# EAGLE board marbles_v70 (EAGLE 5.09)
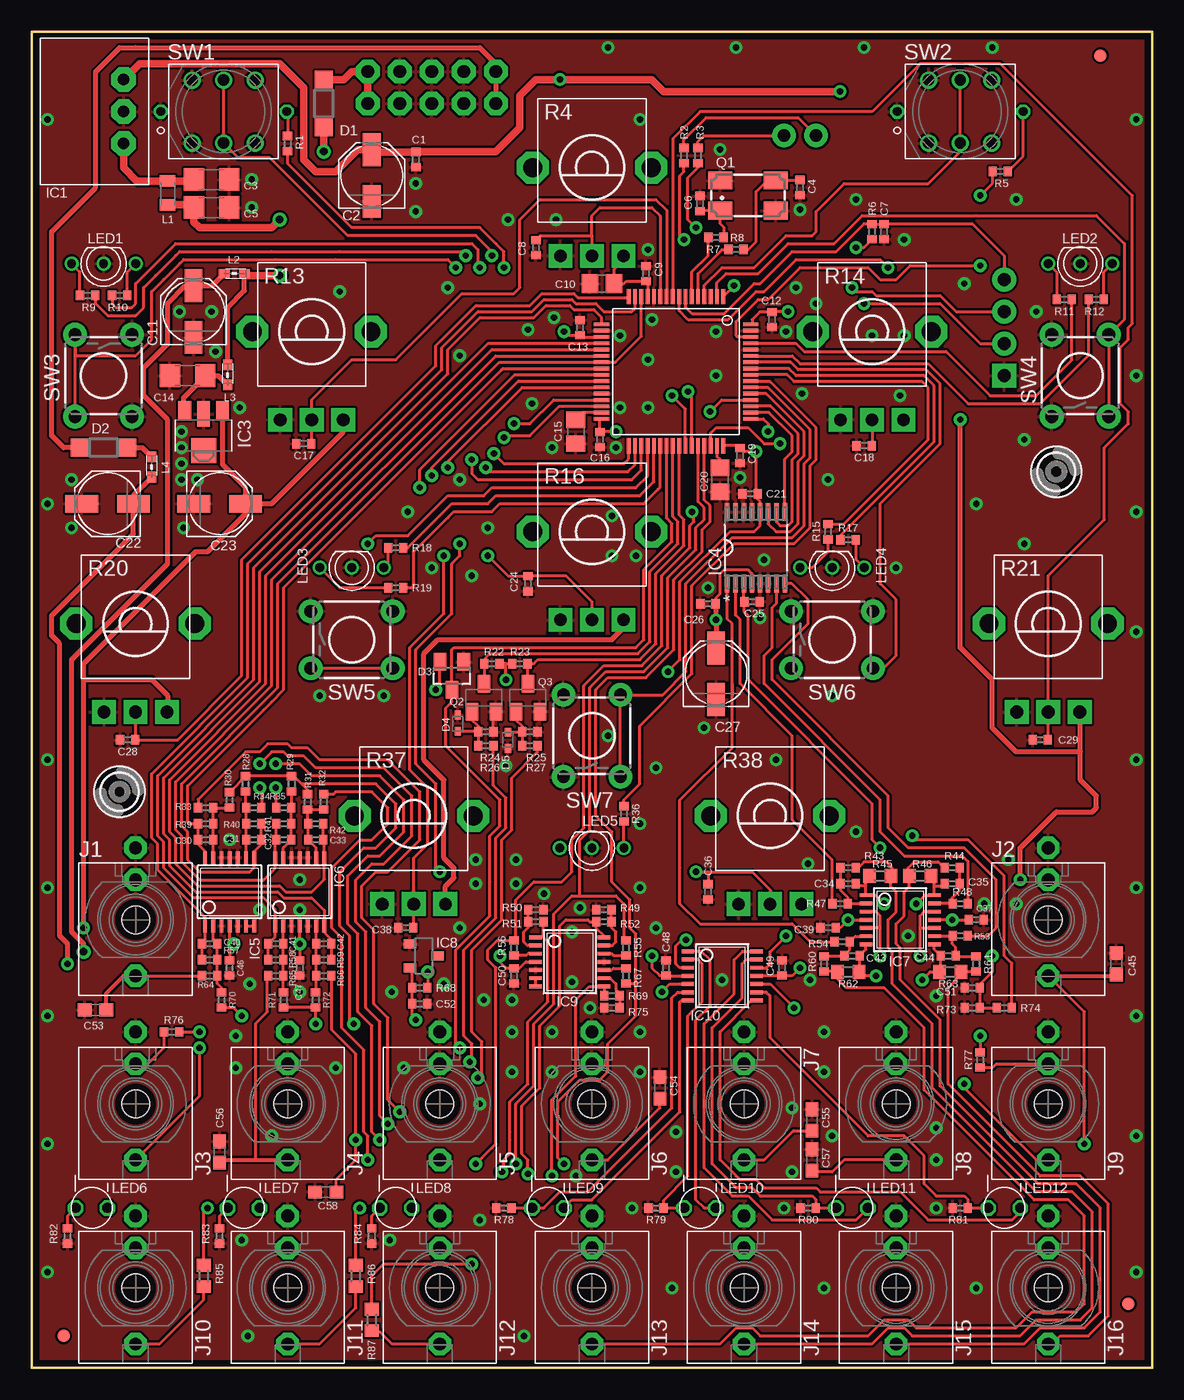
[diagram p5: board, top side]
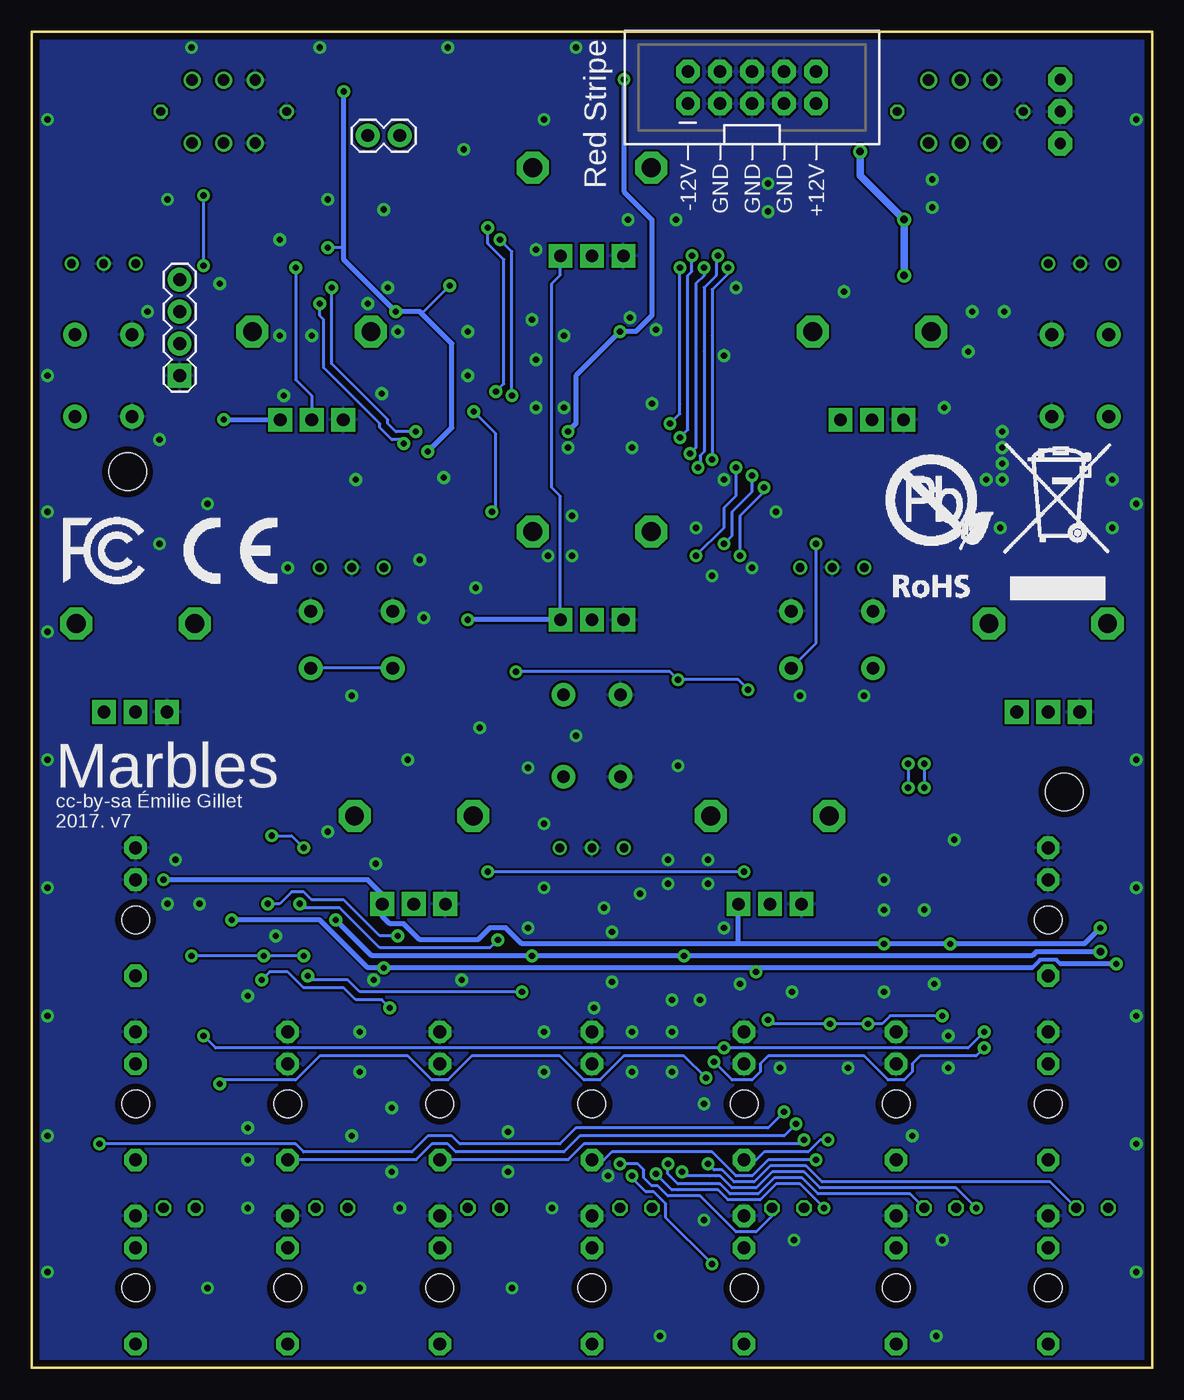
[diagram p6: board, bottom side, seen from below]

Size 88.9 x 106.05 mm. Coordinates in mm from the lower left corner, seen from the top.
Outline: 0,0 88.9,0 88.9,106.05 0,106.05 0,0
Copper layers (1*16): Top 0.035mm / dielectric 1.5mm / Bottom 0.035mm
Design rules "PCBCart-Standard-Fine": minimum track width 8mil, minimum drill 0.4mm, track to track 7mil, track to pad 7mil, pad to pad 7mil, via to via 7mil, smd to smd 7mil, copper to edge 20mil, drill to drill 8mil, minimum pad ring 8mil, minimum via ring 10mil, stop-mask expansion 3mil, vias tented up to drill 25mil, thermal gap 8mil

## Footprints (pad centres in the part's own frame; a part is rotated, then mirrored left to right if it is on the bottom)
C0402 = smd 0.65 x 0.75: 1 -0.6,0; 2 0.6,0
PANASONIC_C = smd 2.6 x 1.4: + 2.05,0; - -2.05,0
C1206 = smd 1.6 x 1.8: 1 -1.4,0; 2 1.4,0
C0805 = smd 1.3 x 1.5: 1 -0.95,0; 2 0.95,0
C0603 = smd 1.1 x 1: 1 -0.85,0; 2 0.85,0
SOD123 = smd 1.4 x 1.4: A 1.9,0; C -1.9,0
SOT23 = smd 1 x 1.4: 1 -0.95,-1.1; 2 0.95,-1.1; 3 0,1.1
SOD523 = smd 0.7 x 0.5: A 0.7,0; C -0.6,0
FIDUCIAL-1X2 = smd 1 x 1: 1 0,0
3,0TINY = hole 3: 0,0
WE78 = drill 0.9 pad 1.93 octagon: 1 -2.54,0; 2 0,0; 3 2.54,0
TQFP-10X10-64 = smd 1.2 x 0.3: 1 -5.936,3.75; 2 -5.936,3.25; 3 -5.936,2.75; 4 -5.936,2.25; 5 -5.936,1.75; 6 -5.936,1.25; 7 -5.936,0.75; 8 -5.936,0.25; 9 -5.936,-0.25; 10 -5.936,-0.75; 11 -5.936,-1.25; 12 -5.936,-1.75; 13 -5.936,-2.25; 14 -5.936,-2.75; 15 -5.936,-3.25; 16 -5.936,-3.75; 33 5.886,-3.75; 34 5.886,-3.25; 35 5.886,-2.75; 36 5.886,-2.25; 37 5.886,-1.75; 38 5.886,-1.25; 39 5.886,-0.75; 40 5.886,-0.25; 41 5.886,0.25; 42 5.886,0.75; 43 5.886,1.25; 44 5.886,1.75; 45 5.886,2.25; 46 5.886,2.75; 47 5.886,3.25; 48 5.886,3.75 | smd 0.3 x 1.2: 17 -3.75,-5.911; 18 -3.25,-5.911; 19 -2.75,-5.911; 20 -2.25,-5.911; 21 -1.75,-5.911; 22 -1.25,-5.911; 23 -0.75,-5.911; 24 -0.25,-5.911; 25 0.25,-5.911; 26 0.75,-5.911; 27 1.25,-5.911; 28 1.75,-5.911; 29 2.25,-5.911; 30 2.75,-5.911; 31 3.25,-5.911; 32 3.75,-5.911; 49 3.75,5.936; 50 3.25,5.936; 51 2.75,5.936; 52 2.25,5.936; 53 1.75,5.936; 54 1.25,5.936; 55 0.75,5.936; 56 0.25,5.936; 57 -0.25,5.936; 58 -0.75,5.936; 59 -1.25,5.936; 60 -1.75,5.936; 61 -2.25,5.936; 62 -2.75,5.936; 63 -3.25,5.936; 64 -3.75,5.936
SOT89 = smd 1 x 1.5: 1 -1.499,-1.981; 3 1.499,-1.981 | smd 1 x 2: 2 0,-1.727 | smd 2 x 2: 2@1 0,1.194
SOP65P640X110-16N = smd 1.422 x 0.356: 1 -2.845,2.286; 2 -2.845,1.626; 3 -2.845,0.965; 4 -2.845,0.33; 5 -2.845,-0.33; 6 -2.845,-0.965; 7 -2.845,-1.626; 8 -2.845,-2.286; 9 2.845,-2.286; 10 2.845,-1.626; 11 2.845,-0.965; 12 2.845,-0.33; 13 2.845,0.33; 14 2.845,0.965; 15 2.845,1.626; 16 2.845,2.286
TSSOP14_065 = smd 0.305 x 0.991: 1 -1.95,-2.718; 2 -1.3,-2.718; 3 -0.65,-2.718; 4 0,-2.718; 5 0.65,-2.718; 6 1.3,-2.718; 7 1.95,-2.718; 8 1.95,2.718; 9 1.3,2.718; 10 0.65,2.718; 11 0,2.718; 12 -0.65,2.718; 13 -1.3,2.718; 14 -1.95,2.718
DBZ_R-PDSO-G3 = smd 0.7 x 1: 1 -0.95,-1.1; 2 0.95,-1.1; 3 0,1.1
WQP_PJ_301M6 = drill 1.016 pad 1.778 octagon: P1 0,-5.715; P2 0,-3.175; P3 0,4.445 | hole 2.2: 0,0
1X04 = drill 1.016 pad 1.88 square: 1 0,0 | drill 1.016 pad 1.88 round: 2 2.54,0; 3 5.08,0; 4 7.62,0
1X02 = drill 1.016 pad 1.88 round: 1 0,0; 2 2.54,0
2X5-SHROUDED = drill 1.016 pad 1.88 octagon: 1 -1.27,5.08; 2 1.27,5.08; 3 -1.27,2.54; 4 1.27,2.54; 5 -1.27,0; 6 1.27,0; 7 -1.27,-2.54; 8 1.27,-2.54; 9 -1.27,-5.08; 10 1.27,-5.08
L2012C = smd 0.9 x 1.25: 1 -0.9,0; 2 1,0
0603 = smd 0.85 x 0.7: 1 -0.9,0; 2 0.7,0
LED-BICOLOR-THROUGHHOLE-2.54 = drill 0.7 round: 1 -2.54,0; 2 0,0; 3 2.54,0
LED3MM = drill 0.813 octagon: 1 -1.27,0; 2 1.27,0
CTS406 = smd 1.9 x 1.4: 1 -2.2,-1.2; 2 2.2,-1.2; 3 2.2,1.2; 4 -2.2,1.2
SOT23-BEC = smd 1 x 1.4: B -0.95,-1.1; C 0,1.1; E 0.95,-1.1
R0402 = smd 0.65 x 0.75: 1 -0.6,0; 2 0.6,0
ALPS_POT_VERTICAL_PS = drill 1 pad 1.88 square: P$1 -2.5,7; P$2 0,7; P$3 2.5,7 | drill 1.5 pad 2.54 octagon: P$4 -4.7,0; P$5 4.7,0
R0603 = smd 1 x 1.1: 1 -0.85,0; 2 0.85,0
LP4OA1PBCT = drill 0.7 octagon: L1 5,0; L2 -5,0 | drill 0.9 round: P1 2.5,2.5; P2 0,2.5; P3 -2.5,2.5; P4 2.5,-2.5; P5 0,-2.5; P6 -2.5,-2.5
TACTILE-PTH = drill 1.016 pad 1.88 round: 1 -3.251,2.261; 2 3.251,2.261; 3 -3.251,-2.261; 4 3.251,-2.261

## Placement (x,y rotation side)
C1  100n  [C0402]  30.48,95.89 270 top
C2  22u  [PANASONIC_C]  26.99,94.61 90 top
C3  22u  [C1206]  14.29,94.3 0 top
C4  20p  [C0402]  60.96,93.66 90 top
C5  22u  [C1206]  14.29,92.08 0 top
C6  20p  [C0402]  53.02,92.39 270 top
C7  100n  [C0402]  67.63,90.17 270 top
C8  100n  [C0402]  40.01,88.9 270 top
C9  100n  [C0402]  48.74,86.84 90 top
C10  2.2u  [C0805]  45.24,86.04 180 top
C11  22u  [PANASONIC_C]  12.86,83.82 90 top
C12  100n  [C0402]  58.74,83.19 270 top
C13  100n  [C0402]  43.5,82.55 90 top
C14  22u  [C1206]  12.38,78.74 180 top
C15  2.2u  [C0805]  43.18,74.3 270 top
C16  100n  [C0402]  45.09,73.66 270 top
C17  100n  [C0402]  21.59,73.34 180 top
C18  100n  [C0402]  66.04,73.18 180 top
C19  100n  [C0402]  56.2,72.39 270 top
C20  2.2u  [C0805]  54.61,70.48 270 top
C21  100n  [C0402]  56.99,69.37 180 top
C22  22u  [PANASONIC_C]  6.03,68.58 180 top
C23  22u  [PANASONIC_C]  14.92,68.58 0 top
C24  100n  [C0402]  39.37,62.23 270 top
C25  470n  [C0402]  57.15,60.8 0 top
C26  100n  [C0402]  53.66,60.64 180 top
C27  22u  [PANASONIC_C]  54.29,55.09 90 top
C28  100n  [C0402]  7.62,49.85 180 top
C29  100n  [C0402]  80.01,49.85 180 top
C30  4.7n  [C0402]  13.81,41.91 180 top
C31  470p  [C0402]  17.62,41.91 0 top
C32  4.7n  [C0402]  20,41.91 180 top
C33  4.7n  [C0402]  22.54,41.91 0 top
C34  47p  [C0402]  64.77,38.42 0 top
C35  47p  [C0402]  73.03,38.42 180 top
C36  100n  [C0402]  53.66,37.78 270 top
C37  100n  [C0402]  74.93,35.56 180 top
C38  100n  [C0402]  29.69,34.92 180 top
C39  100n  [C0402]  63.18,34.92 180 top
C40  4.7n  [C0402]  14.13,33.66 180 top
C41  470p  [C0402]  19.37,33.66 180 top
C42  4.7n  [C0402]  23.18,33.66 0 top
C43  47p  [C0402]  65.09,32.7 0 top
C44  47p  [C0402]  72.71,32.7 180 top
C45  ESD  [C0603]  86.04,32.07 90 top
C46  100n  [C0402]  15.72,31.75 270 top
C47  100n  [C0402]  21.27,31.75 270 top
C48  100n  [C0402]  50.32,31.75 90 top
C49  100n  [C0402]  59.53,31.75 270 top
C50  100n  [C0402]  38.26,31.12 270 top
C51  470n  [C0402]  74.61,30.16 180 top
C52  470n  [C0402]  30.8,28.89 0 top
C53  ESD  [C0603]  5.08,28.42 180 top
C54  ESD  [C0603]  49.85,22.23 90 top
C55  ESD  [C0603]  61.91,19.68 90 top
C56  ESD  [C0603]  14.92,17.14 90 top
C57  ESD  [C0603]  61.91,16.51 90 top
C58  ESD  [C0603]  23.34,13.97 180 top
D1  1N5819HW  [SOD123]  23.18,100.33 90 top
D2  1N5819HW  [SOD123]  5.71,73.03 0 top
D3  BAT54S  [SOT23]  33.34,54.93 180 top
D4  1N4148  [SOD523]  33.81,51.12 90 top
D5  1N4148  [SOD523]  37.78,49.85 270 top
F1  FIDUCIAL1X2  [FIDUCIAL-1X2]  84.77,104.14 0 top
F2  FIDUCIAL1X2  [FIDUCIAL-1X2]  87,5.08 0 top
F3  FIDUCIAL1X2  [FIDUCIAL-1X2]  2.54,2.54 0 top
H3  MOUNT-HOLE3.0TINY  [3,0TINY]  81.28,71.12 0 top
H5  MOUNT-HOLE3.0TINY  [3,0TINY]  6.99,45.72 0 top
IC1  R-78E3.3-0.5  [WE78]  7.3,99.69 90 top
IC2  STM32F405RGT6  [TQFP-10X10-64]  51.12,79.06 270 top
IC3  LD2981ABU33  [SOT89]  13.65,73.98 180 top
IC4  DAC8164ICPW  [SOP65P640X110-16N]  57.47,65.09 90 top
IC5  MCP6004  [TSSOP14_065]  15.72,37.78 0 top
IC6  MCP6004  [TSSOP14_065]  21.27,37.78 0 top
IC7  OPA4171  [TSSOP14_065]  68.9,35.56 270 top
IC8  LM4040B10  [DBZ_R-PDSO-G3]  31.11,32.7 270 top
IC9  LM324PW  [TSSOP14_065]  42.7,32.23 270 top
IC10  TL074PW  [TSSOP14_065]  54.77,31.11 270 top
J1  PJ301_THONKICONN6  [WQP_PJ_301M6]  8.26,35.56 180 top
J2  PJ301_THONKICONN6  [WQP_PJ_301M6]  80.64,35.56 180 top
J3  PJ301_THONKICONN6  [WQP_PJ_301M6]  8.26,20.95 180 top
J4  PJ301_THONKICONN6  [WQP_PJ_301M6]  20.32,20.95 180 top
J5  PJ301_THONKICONN6  [WQP_PJ_301M6]  32.38,20.95 180 top
J6  PJ301_THONKICONN6  [WQP_PJ_301M6]  44.45,20.95 180 top
J7  PJ301_THONKICONN6  [WQP_PJ_301M6]  56.52,20.95 180 top
J8  PJ301_THONKICONN6  [WQP_PJ_301M6]  68.58,20.95 180 top
J9  PJ301_THONKICONN6  [WQP_PJ_301M6]  80.64,20.95 180 top
J10  PJ301_THONKICONN6  [WQP_PJ_301M6]  8.26,6.35 180 top
J11  PJ301_THONKICONN6  [WQP_PJ_301M6]  20.32,6.35 180 top
J12  PJ301_THONKICONN6  [WQP_PJ_301M6]  32.38,6.35 180 top
J13  PJ301_THONKICONN6  [WQP_PJ_301M6]  44.45,6.35 180 top
J14  PJ301_THONKICONN6  [WQP_PJ_301M6]  56.52,6.35 180 top
J15  PJ301_THONKICONN6  [WQP_PJ_301M6]  68.58,6.35 180 top
J16  PJ301_THONKICONN6  [WQP_PJ_301M6]  80.64,6.35 180 top
JP1  [1X04]  77.15,78.74 90 bottom
JP2  [1X02]  59.69,97.79 180 bottom
JP4  M05X2SHD  [2X5-SHROUDED]  31.75,101.6 90 bottom
L1  33u  [L2012C]  10.79,93.19 90 top
L2  [0603]  16.19,86.84 0 top
L3  [0603]  15.56,78.9 90 top
L4  [0603]  9.53,71.6 90 top
LED1  W115WSURKMGKW  [LED-BICOLOR-THROUGHHOLE-2.54]  5.71,87.63 180 top
LED2  W115WSURKMGKW  [LED-BICOLOR-THROUGHHOLE-2.54]  83.19,87.63 180 top
LED3  W115WSURKMGKW  [LED-BICOLOR-THROUGHHOLE-2.54]  25.4,63.5 180 top
LED4  W115WSURKMGKW  [LED-BICOLOR-THROUGHHOLE-2.54]  63.5,63.5 180 top
LED5  W115WSURKMGKW  [LED-BICOLOR-THROUGHHOLE-2.54]  44.45,41.27 180 top
LED6  WP937EGW  [LED3MM]  4.76,12.7 180 top
LED7  WP937EGW  [LED3MM]  16.83,12.7 180 top
LED8  WP937EGW  [LED3MM]  28.89,12.7 180 top
LED9  WP937EGW  [LED3MM]  40.96,12.7 180 top
LED10  WP937EGW  [LED3MM]  53.02,12.7 180 top
LED11  WP937EGW  [LED3MM]  65.09,12.7 180 top
LED12  WP937EGW  [LED3MM]  77.15,12.7 180 top
Q1  8MHz  [CTS406]  56.83,93.03 0 top
Q2  MMBT3904  [SOT23-BEC]  35.88,53.18 0 top
Q3  MMBT3904  [SOT23-BEC]  39.37,53.18 0 top
R1  39  [R0402]  20.32,97.16 90 top
R2  100  [R0402]  51.75,96.2 270 top
R3  100  [R0402]  52.86,96.2 270 top
R4  10kB  [ALPS_POT_VERTICAL_PS]  44.45,95.25 180 top
R5  39  [R0402]  76.83,94.93 0 top
R6  10k  [R0402]  66.67,90.17 270 top
R7  100  [R0402]  54.29,89.69 0 top
R8  100  [R0402]  55.88,88.74 0 top
R9  2.2k  [R0402]  4.45,85.09 180 top
R10  1.5k  [R0402]  6.99,85.09 0 top
R11  2.2k  [R0402]  81.92,84.77 180 top
R12  1.5k  [R0402]  84.45,84.77 0 top
R13  10kB  [ALPS_POT_VERTICAL_PS]  22.23,82.23 180 top
R14  10kB  [ALPS_POT_VERTICAL_PS]  66.67,82.23 180 top
R15  2.2k  [R0402]  63.18,66.36 270 top
R16  10kB  [ALPS_POT_VERTICAL_PS]  44.45,66.36 180 top
R17  1.5k  [R0402]  64.77,65.72 0 top
R18  1.5k  [R0402]  28.89,65.09 180 top
R19  2.2k  [R0402]  28.89,61.91 180 top
R20  10kB  [ALPS_POT_VERTICAL_PS]  8.26,59.05 180 top
R21  10kB  [ALPS_POT_VERTICAL_PS]  80.64,59.05 180 top
R22  10k  [R0402]  36.51,55.88 0 top
R23  10k  [R0402]  38.74,55.88 180 top
R24  100k  [R0402]  36.04,50.48 180 top
R25  100k  [R0402]  39.53,50.48 180 top
R26  100k  [R0402]  36.04,49.37 180 top
R27  100k  [R0402]  39.53,49.37 180 top
R28  200k  [R0402]  16.99,46.35 90 top
R29  200k  [R0402]  20.64,46.35 90 top
R30  200k  [R0402]  15.72,45.09 90 top
R31  200k  [R0402]  21.91,44.93 90 top
R32  100k  [R0402]  23.18,44.93 90 top
R33  100k  [R0402]  13.81,44.45 180 top
R34  100k  [R0402]  17.62,44.45 0 top
R35  100k  [R0402]  20,44.45 180 top
R36  1.5k  [R0402]  46.99,43.97 270 top
R37  10kB  [ALPS_POT_VERTICAL_PS]  30.32,43.81 180 top
R38  10kB  [ALPS_POT_VERTICAL_PS]  58.58,43.81 180 top
R39  33k  [R0402]  13.81,43.18 0 top
R40  33k  [R0402]  17.62,43.18 180 top
R41  33k  [R0402]  20,43.18 0 top
R42  33k  [R0402]  22.54,43.18 180 top
R43  100k  [R0402]  64.77,39.69 180 top
R44  100k  [R0402]  73.02,39.69 0 top
R45  1.0k  [R0603]  67.31,39.05 180 top
R46  1.0k  [R0603]  70.48,39.05 0 top
R47  23.7k  [R0402]  64.14,36.83 180 top
R48  23.7k  [R0402]  73.66,36.83 0 top
R49  39k  [R0402]  45.4,36.35 180 top
R50  39k  [R0402]  40.01,36.35 0 top
R51  56k  [R0402]  40.01,35.4 180 top
R52  56k  [R0402]  45.4,35.4 0 top
R53  23.7k  [R0402]  73.66,34.29 0 top
R54  23.7k  [R0402]  64.29,33.81 180 top
R55  10k  [R0402]  47.15,33.34 90 top
R56  10k  [R0402]  38.26,33.34 90 top
R57  33k  [R0402]  14.13,32.38 0 top
R58  33k  [R0402]  19.37,32.38 0 top
R59  33k  [R0402]  23.18,32.38 180 top
R60  100k  [R0402]  62.87,32.07 90 top
R61  100k  [R0402]  74.93,32.07 90 top
R62  1.0k  [R0603]  64.77,31.43 0 top
R63  1.0k  [R0603]  72.87,31.43 180 top
R64  100k  [R0402]  14.13,31.11 180 top
R65  100k  [R0402]  19.37,31.11 180 top
R66  100k  [R0402]  23.18,31.11 0 top
R67  10k  [R0402]  47.15,31.11 270 top
R68  1.0k  [R0402]  30.8,30.16 180 top
R69  56k  [R0402]  46.04,29.53 0 top
R70  200k  [R0402]  15.08,29.21 270 top
R71  200k  [R0402]  20,29.21 270 top
R72  200k  [R0402]  22.54,29.21 270 top
R73  100k  [R0402]  74.61,28.57 0 top
R74  150k  [R0402]  77.15,28.57 0 top
R75  39k  [R0402]  46.04,28.57 180 top
R76  100k  [R0402]  11.11,26.67 180 top
R77  100k  [R0402]  75.25,24.45 270 top
R78  680  [R0402]  37.47,12.7 180 top
R79  680  [R0402]  49.53,12.7 180 top
R80  680  [R0402]  61.59,12.7 180 top
R81  680  [R0402]  73.66,12.7 180 top
R82  180  [R0402]  2.86,10.48 90 top
R83  180  [R0402]  14.92,10.48 90 top
R84  180  [R0402]  26.99,10.48 90 top
R85  1.0k  [R0603]  13.65,7.3 90 top
R86  1.0k  [R0603]  25.72,7.3 90 top
R87  1.0k  [R0603]  26.99,3.81 90 top
SW1  LP4OA1PBCT  [LP4OA1PBCT]  15.24,99.69 0 top
SW2  LP4OA1PBCT  [LP4OA1PBCT]  73.66,99.69 0 top
SW3  [TACTILE-PTH]  5.71,78.74 270 top
SW4  [TACTILE-PTH]  83.19,78.74 90 top
SW5  [TACTILE-PTH]  25.4,57.78 0 top
SW6  [TACTILE-PTH]  63.5,57.78 0 top
SW7  [TACTILE-PTH]  44.45,50.16 90 top
U$2  [ROHS_BIG]  22.38,60.17 0 bottom
U$4  [CE_MEDIUM]  76.83,62.23 0 bottom
U$5  [FCC_MEDIUM]  86.36,62.23 0 bottom

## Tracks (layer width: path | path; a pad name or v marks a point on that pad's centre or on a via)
+3V3  (via drill 0.5)
  Top 0.254: IC2.64 57.15,82.9 57.15,83.19 57.75,83.78 C12.1 58.77,83.82 v60.01,83.82 | v46.35,74.3 45.12,74.3 C16.1 45.09,75.19 IC2.32 | IC2.1 55.72,85.85 v55.72,85.88 | R6.2 66,88.9 v65.41,88.9 | IC2.48 56.02,73.17 C19.1 56.48,72.71 v57.47,72.71 57.47,69.5 C21.1 57.59,68.93 57.78,68.74 57.78,67.94 IC4.12 57.8,66.85 57.31,66.36 55.4,66.36 51.44,62.39 51.44,56.2 v50.48,55.24 | v50.48,55.24 | R22.2 37.62,55.88 | v32.07,53.82 32.39,54.14 D3.2 | v37.62,54.61 37.62,55.88 | R23.2 | 37.62,55.88 R23.2 | IC2.19 43.64,81.81 C13.1 42.51,81.95 v42.23,82.23
  Top 0.61: v41.91,102.23 49.21,102.23 50.16,101.28 v64.14,101.28 | v41.91,102.23 41.88,102.2 | IC1.3 8.57,103.5 19.68,103.5 21.59,101.6 21.59,95.89 22.54,94.93 24.13,94.93 25.86,96.67 C2.+ 27.17,96.48 C1.1 30.52,96.52 36.83,96.52 38.73,98.42 38.73,100.97 40.01,102.23 v41.91,102.23
  Bottom 0.254: v55.72,85.88 57.78,83.82 v60.01,83.82 | 64.14,88.9 v65.41,88.9 | v32.07,53.82 32.86,54.61 v37.62,54.61 38.26,55.24 v50.48,55.24
  Bottom 0.406: v57.47,72.71 55.56,74.61 55.56,81.28 58.1,83.82 v60.01,83.82 64.14,87.95 64.14,88.9 v64.14,101.28 | v41.91,102.23 41.91,93.34 39.69,91.12 39.69,83.5 40.96,82.23 v42.23,82.23 45.72,78.74 45.72,74.93 v46.35,74.3
+3V3_A  (via drill 0.5)
  Top 0.254: C47.1 v21.27,33.66 IC6.4 | C26.1 54.29,60.68 54.29,61.12 54.61,61.44 54.61,63.02 54.93,63.34 56.83,63.34 57.14,63.04 IC4.4 | R4.P$1 46.95,87.91 46.19,87.15 C10.1 46.99,86.04 47.18,86.24 C9.1 48.87,86.11 IC2.13 | IC5.4 15.72,33.97 v16.03,33.66 15.72,33.34 C46.1
  Top 0.406: v78.42,38.73 78.42,41.27 81.28,44.13 84.14,44.13 84.45,44.45 84.45,45.4 83.19,46.67 83.19,48.9 | v4.13,34.92 4.13,54.61 | R13.P$1 24.73,74.25 19.05,68.58 C23.+ | 4.13,54.61 4.13,55.88 13.02,64.77 13.97,64.77 16.97,67.77 C23.+ | R20.P$1 10.79,52.09 10.79,53.34 9.53,54.61 4.13,54.61 | C26.1 54.29,60.61 v54.29,59.37 C27.+ | R16.P$1 46.95,58.78 46.99,58.74 46.04,57.78 32.23,57.78 31.11,56.67 31.11,48.26 32.7,46.67 32.7,40.48 33.5,39.69 33.5,38.89 32.82,38.22 R37.P$1 | v73.66,75.25 73.66,57.15 76.2,54.61 76.2,50.8 78.11,48.9 83.19,48.9 | R21.P$1 83.19,52.05 83.19,48.9 | C23.+ 16.99,68.58 16.99,69.85 16.35,70.48 15.15,71.69 IC3.1
  Bottom 0.254: R16.P$1 46.95,69.17 47.62,69.85 47.62,86.04 46.95,86.72 R4.P$1
  Bottom 0.406: v4.13,34.92 5.4,33.66 v16.03,33.66 v21.27,33.66 32.86,33.66 | R37.P$1 32.86,36.77 32.86,33.66 | R14.P$1 69.19,75.25 v73.66,75.25 | 32.86,33.66 50.01,33.66 51.28,34.92 52.55,34.92 53.5,33.97 58.1,33.97 59.37,35.24 60.48,35.24 61.08,35.84 R38.P$1 61.08,37.58 62.23,38.73 v78.42,38.73 | 46.97,59.37 R16.P$1 46.97,59.37 v54.29,59.37
ADC_DV_CV
  Top 0.254: IC2.21 36.52,80.81 18.57,62.87 18.57,54.29 10.95,46.67 10.95,42.55 11.43,42.07 11.43,40.01 13.18,38.26 19.68,38.26 20.16,37.78 22.23,37.78 23.18,38.73 23.22,38.78 IC6.8 23.22,41.83 23.18,41.88 C33.2 R42.1
ADC_DV_POT
  Top 0.254: 44.47,88.27 R4.P$2 44.45,89.85 | 44.45,89.85 44.45,91.44 45.09,92.08 49.21,92.08 49.87,91.42 IC2.11 | C8.1 40.36,89.85 44.45,89.85
ADC_LENGTH_POT  (via drill 0.5)
  Top 0.254: IC2.27 38.91,77.81 33.02,71.91 v33.02,71.44 | v36.2,64.45 37.82,62.83 C24.1 39.41,62.87 42.39,62.87 44.45,60.8 R16.P$2
  Bottom 0.254: v33.02,71.44 33.02,69.22 33.97,68.26 33.97,66.67 v36.2,64.45
ADC_T_BIAS_CV
  Top 0.254: IC2.15 47.87,84.06 47.62,83.82 45.4,83.82 44.77,84.45 43.18,84.45 42.86,84.77 40.64,84.77 40.16,84.3 39.69,83.82 35.4,83.82 32.54,80.96 32.54,79.22 25.24,71.91 17.14,63.82 17.14,54.77 9.53,47.15 9.53,42.07 10,41.59 | R57.1 C40.2 13.77,33.89 13.77,34.45 | 10,41.59 10,39.53 13.77,35.76 13.77,34.45 | 10,41.59 | 13.77,34.45 IC5.1
ADC_T_BIAS_POT
  Top 0.254: R20.P$2 8.26,49.88 C28.1 11.59,49.85 16.67,54.93 16.67,64.14 32.07,79.53 32.07,81.12 35.24,84.3 39.53,84.3 40.48,85.25 43.02,85.25 43.34,84.93 47.31,84.93 IC2.16
ADC_T_JITTER_CV
  Top 0.254: IC2.20 36.22,81.31 18.1,63.18 18.1,54.45 10.48,46.83 10.48,42.39 10.95,41.91 | R59.1 C42.2 23.78,34.01 23.22,34.56 IC6.7 23.22,36.31 23.18,36.35 22.23,37.31 20,37.31 19.53,37.78 13.02,37.78 10.95,39.85 10.95,41.91 | 10.95,41.91
ADC_T_JITTER_POT  (via drill 0.5)
  Top 0.254: IC2.25 38.33,78.81 30.8,71.28 v30.8,69.85 | C38.1 30.32,34.96 R37.P$2 30.32,40.48 | 30.32,40.48 31.43,41.59 31.43,46.04 30,47.47 | v32.7,64.45 32.7,59.85 30,57.15 30,47.47 | 30.32,40.48 | 30,47.47
  Bottom 0.254: v30.8,69.85 30.8,69.53 32.7,67.63 v32.7,64.45
ADC_T_RATE_CV
  Top 0.254: R58.1 C41.2 19.32,34.21 IC6.1 19.32,36.4 18.41,37.31 12.86,37.31 10.48,39.69 10.48,41.75 10,42.23 10,46.99 17.62,54.61 17.62,63.5 33.02,78.9 33.02,80.8 35.56,83.34 39.85,83.34 40.32,83.82 40.8,84.3 42.07,84.3 42.7,84.3 43.02,83.98 44.61,83.98 45.21,83.38 IC2.17
ADC_T_RATE_POT
  Top 0.254: R13.P$2 22.23,76.2 | C17.1 22.23,73.38 R13.P$2 | IC2.10 50.37,91.87 49.53,92.71 40.32,92.71 38.73,91.12 38.73,85.72 38.26,85.25 34.13,85.25 | 34.13,85.25 | 34.13,85.25 28.89,80.01 25.4,80.01 22.23,76.83 R13.P$2
ADC_X_BIAS_CV
  Top 0.254: IC2.24 37.4,79.31 37.26,79.17 27.15,69.06 20,61.91 20,53.82 19.05,52.86 18.41,52.23 12.38,46.2 12.38,43.34 12.54,43.18 R39.1 C30.2 13.18,41.88 13.18,41.59 13.77,41 IC5.14
ADC_X_BIAS_POT
  Top 0.254: IC2.9 50.87,97.54 53.02,99.69 66.67,99.69 70.48,103.5 76.83,103.5 87.31,93.03 87.31,82.87 87,82.55 87,81.6 86.36,80.96 86.36,76.52 87,75.88 87,74.93 85.09,73.03 85.09,67.31 80.64,62.87 R21.P$2 80.64,49.88 C29.1
ADC_X_SPREAD_CV
  Top 0.254: R40.1 C31.2 18.26,41.88 18.26,41.59 17.67,41 IC5.8 17.67,39.73 17.3,39.37 13.34,39.37 12.38,40.32 12.38,42.55 11.91,43.02 11.91,46.35 19.53,53.98 19.53,62.23 37.1,79.81 IC2.23 46.31,79.81 48.37,81.86 IC2.14
ADC_X_SPREAD_POT  (via drill 0.5)
  Top 0.254: IC2.8 51.37,83.89 52.07,83.19 55.24,83.19 57.47,85.41 58.1,85.41 60.64,87.95 67.31,87.95 v67.94,87.31 | C18.1 66.67,73.22 R14.P$2
  Bottom 0.254: v67.94,87.31 67.94,78.42 66.67,77.15 R14.P$2
ADC_X_STEPS_CV
  Top 0.254: R41.1 C32.2 19.37,41.88 19.32,41.83 IC6.14 19.32,39.64 18.41,38.73 13.34,38.73 11.91,40.16 11.91,42.23 | IC2.22 36.81,80.31 19.05,62.55 19.05,54.13 11.43,46.51 11.43,42.7 11.91,42.23 | 11.91,42.23 | 11.91,42.23
ADC_X_STEPS_POT  (via drill 0.5)
  Top 0.254: IC2.26 38.62,78.31 31.75,71.44 v31.75,70.8 | v33.97,65.41 33.97,64.45 33.34,63.82 33.34,59.85 30.48,56.99 30.48,47.94 32.07,46.35 32.07,39.69 v32.38,39.37 | v52.7,39.37 53.66,39.37 | 53.66,39.37 57.15,39.37 58.58,37.94 R38.P$2 | 53.66,39.37 C36.1
  Bottom 0.254: v31.75,70.8 31.75,69.53 33.34,67.94 33.34,66.04 v33.97,65.41 | v32.38,39.37 v52.7,39.37
AREF_-10  (via drill 0.5)
  Top 0.254: R71.2 R72.2 v22.54,27.3 | R30.2 R28.2 R29.2 20.76,46.83 20.95,46.83 21.43,46.35 | v25.56,27.3 25.24,27.62 25.24,34.29 24.45,35.08 24.45,39.37 26.35,41.27 27.3,41.27 28.89,42.86 28.89,44.77 27.3,46.35 21.43,46.35 | v30.48,27.62 30.2,27.91 C52.1 R68.2 30.2,31.57 IC8.2 | v16.67,27.94 16,28.61 R70.2 | 21.43,46.35 21.91,45.88 R31.2
  Bottom 0.254: v16.67,27.94 20.8,27.94 21.43,27.3 v22.54,27.3 v25.56,27.3 30.16,27.3 v30.48,27.62
DAC_MOSI
  Top 0.254: IC2.53 58.27,77.31 61.28,74.3 61.28,72.39 60.8,71.91 60.8,66.99 60.17,66.36 59.05,66.36 58.43,66.98 IC4.11
DAC_SCK
  Top 0.254: IC2.51 58.63,76.31 60.8,74.14 60.8,72.55 60.33,72.07 60.33,67.15 60.01,66.83 59.37,66.83 59.09,67.11 IC4.10
DAC_SS
  Top 0.254: IC2.50 58.49,75.81 60.33,73.98 60.33,72.71 59.75,72.14 IC4.9
DAC_X_1
  Top 0.254: R47.2 63.5,36.87 63.5,40.32 60.33,43.5 60.33,50.16 56.2,54.29 56.2,59.37 55.84,59.73 IC4.2
DAC_X_2
  Top 0.254: R48.2 74.26,40.2 73.82,40.64 69.22,40.64 67.31,42.55 67.31,45.09 58.1,54.29 58.1,56.52 58.74,57.15 58.74,60.33 59.09,60.68 IC4.7
DAC_X_3
  Top 0.254: R53.2 75.88,34.29 76.52,34.92 76.52,38.73 73.98,41.27 69.53,41.27 67.94,42.86 67.94,45.4 58.74,54.61 58.74,56.2 61.59,59.05 61.59,59.37 61.59,60.96 60.31,62.24 IC4.8
DAC_Y
  Top 0.254: IC4.1 55.18,59.44 55.56,59.05 55.56,54.29 | R54.2 | R54.2 61.75,33.81 60.33,35.24 53.02,35.24 51.44,36.83 51.44,39.69 51.44,45.09 55.56,49.21 55.56,54.29 | 55.56,54.29 55.56,53.34
DEPRECATED
  Top 0.254: IC5.6 IC5.7
GATE_T_1  (via drill 0.5)
  Top 0.254: v52.39,67.94 52.55,67.79 52.55,67.15 52.23,66.83 52.23,65.09 50.01,62.87 50.01,57.31 48.42,55.72 45.4,55.72 43.81,54.13 43.81,42.86 42.86,41.91 42.86,39.37 42.07,38.58 39.85,38.58 38.42,37.15 38.42,34.1 R56.2 | v35.24,16.19 35.72,16.67 36.51,17.46 36.83,17.78 36.83,31.75 36.2,32.38 36.2,33.18 36.95,33.94 R56.2 | R56.2 38.22,33.97 | R56.2 38.1,34.1 | v53.82,75.88 54.74,76.81 IC2.52
  Bottom 0.254: v53.82,75.88 52.07,74.14 52.07,68.26 v52.39,67.94 | LED6.1 8.1,14.76 26.19,14.76 27.46,16.03 30.32,16.03 31.59,14.76 33.18,14.76 34.13,15.72 34.77,15.72 v35.24,16.19
GATE_T_2  (via drill 0.5)
  Top 0.254: IC2.44 52.87,68.73 53.34,68.26 53.34,67.31 52.7,66.67 52.7,64.93 50.48,62.71 50.48,57.15 48.58,55.24 45.56,55.24 44.29,53.98 44.29,42.7 43.5,41.91 43.5,37.47 | v38.42,16.19 38.42,20.95 39.85,22.38 39.85,27.3 41.43,28.89 41.43,36.04 42.86,37.47 43.5,37.47 | R55.2 46.99,34.1 46.99,36.83 46.35,37.47 43.5,37.47
  Bottom 0.254: LED7.1 19.21,13.81 26.51,13.81 27.78,15.08 30,15.08 31.27,13.81 33.5,13.81 34.29,14.61 37.62,14.61 38.42,15.4 v38.42,16.19
GATE_T_3  (via drill 0.5)
  Top 0.254: v42.23,16.19 41.75,16.67 41.75,21.11 43.5,22.86 45.09,22.86 45.72,23.5 45.72,25.72 47.94,27.94 47.94,30.48 | IC2.45 53.37,68.87 53.82,68.42 53.82,67.15 53.37,66.7 53.18,66.52 53.18,64.77 50.96,62.55 50.96,56.99 48.74,54.77 45.72,54.77 44.77,53.82 44.77,43.81 46.04,42.55 46.04,38.58 47.47,37.15 47.47,34.92 47.94,34.45 47.94,30.48 | R67.2 47.18,30.48 47.94,30.48
  Bottom 0.254: LED8.1 30.16,12.06 31.43,10.79 33.02,10.79 35.88,13.65 38.42,13.65 39.21,14.45 39.69,14.45 40.32,15.08 40.32,15.72 40.8,16.19 v42.23,16.19
GND  (via drill 0.5)
  Top 0.254: Q2.E 36.64,51.89 R24.1
  other vias: 63.18,70.48 62.23,84.45 75.56,36.83 41.59,91.12 17.3,30.48 21.27,29.84 15.72,41.91 21.27,38.73 21.27,36.35 41.43,83.34 30.48,91.76 30.48,93.98 60.96,91.92 35.56,11.75 47.62,12.7 59.69,12.7 71.75,12.7 61.75,30.8 46.35,73.03 33.97,34.92 32.7,30.48 38.1,29.21 48.26,23.5 29.53,23.81 24.13,23.81 28.42,10.16 16.67,10.16 62.87,26.67 62.87,23.5 60.33,20.64 60.33,15.56 51.12,18.73 51.12,15.56 49.53,34.92 49.53,47.62 58.1,64.14 61.59,40.01 78.11,36.83 77.47,40.32 46.67,81.92 39.69,76.52 39.37,82.39 24.45,85.41 33.02,85.72 37.78,91.12 29.84,67.94 46.67,76.2 49.21,83.19 65.41,92.71 47.94,64.45 46.04,64.45 60.64,85.72 69.22,89.53 1.27,7.62 1.27,17.78 1.27,27.94 1.27,38.1 1.27,48.26 45.72,104.78 87.63,7.62 87.63,18.41 87.63,27.94 87.63,38.1 87.63,58.42 87.63,67.94 87.63,78.74 22.86,53.34 59.05,48.26 48.26,99.06 74.93,68.58 78.74,65.41 39.05,2.54 17.14,2.54 50.8,6.35 62.87,6.35 74.93,6.35 48.9,80.01 54.29,78.74 48.9,76.2 54.29,82.23 41.27,73.03 16.19,26.35 16.19,23.81 54.77,30.8 69.53,34.29 71.75,29.53 78.11,92.71 79.69,83.82 37.62,47.78 46.04,67.63 19.05,18.41 66.67,81.92 69.22,81.92 48.26,38.1 48.9,88.74 87.63,48.26 59.85,82.23 54.61,96.68 63.5,18.41 71.75,19.05 71.75,16.51 35.56,20.95 68.9,77.15 73.98,86.04 56.2,70.64 48.26,26.67 44.29,28.57 42.86,30.64 43.5,36.51 40.64,37.62 42.86,34.61 35.88,29.21 41.27,23.5 41.27,26.67 38.1,26.67 38.1,23.5 17.46,94.3 17.46,92.08 27.94,53.34 78.74,73.66 43.18,15.24 11.75,83.82 14.29,83.82 14.61,80.64 11.91,70.48 12.06,66.67 3.17,70.48 3.17,66.67 1.27,68.58 33.97,80.33 53.66,61.91 53.34,50.8 36.2,66.67 34.92,62.87 31.75,63.5 33.97,70.48 57.78,59.53 18.1,36.35 38.42,38.42 38.42,40.32 35.24,40.32 35.24,38.42 28.57,29.84 68.58,63.5 63.5,53.34 65.41,42.55 48.26,43.18 45.72,50.16 61.12,77.31 55.88,104.78 66.04,104.78 76.2,104.78 87.63,99.06 1.27,99.06 11.91,74.3 11.91,73.03 11.91,71.76 13.18,70.48 16.51,76.2
  pour Bottom: 0,106.05 0,0 88.9,0 88.9,106.05
  pour Top: 0,106.05 88.9,106.05 88.9,0 0,0
LED_T_DV  (via drill 0.5)
  Top 0.254: v37.47,87.31 37.47,88.27 37.47,88.58 36.83,89.22 35.56,90.49 25.4,90.49 20.32,95.57 R1.1 | v38.26,74.93 39.53,74.93 41.41,76.81 IC2.29
  Bottom 0.254: v38.26,74.93 37.47,75.72 37.47,76.52 v37.47,87.31
LED_T_MODE_G  (via drill 0.5)
  Top 0.254: IC2.33 47.37,72.13 46.99,71.75 37.47,71.75 v36.67,72.55 | v35.56,87.31 35.4,87.47 35.4,88.74 34.92,89.22 11.43,89.22 8.26,86.04 8.26,84.45 7.94,84.14 6.67,84.14 6.38,84.42 R10.1
  Bottom 0.254: v36.67,72.55 36.2,73.03 36.2,86.04 35.56,86.68 v35.56,87.31
LED_T_MODE_R  (via drill 0.5)
  Top 0.254: IC2.34 47.87,71.68 47.31,71.12 36.35,71.12 v36.04,71.44 | v34.45,88.27 34.45,88.42 34.29,88.58 24.45,88.58 19.05,88.58 11.75,88.58 11.43,88.27 9.84,86.68 8.89,85.72 8.89,84.14 8.26,83.5 6.03,83.5 | 6.03,83.5 6.35,83.5 | 6.03,83.5 5.04,84.49 R9.1
  Bottom 0.254: v36.04,71.44 35.88,71.6 35.88,72.39 35.56,72.71 35.56,80.64 35.56,85.72 34.61,86.68 34.61,88.11 v34.45,88.27
LED_T_RANGE_G
  Top 0.254: 29.84,65.09 | R18.1 29.84,65.09 | 29.84,65.09 33.34,68.58 36.2,68.58 36.83,69.22 48.26,69.22 49.37,70.32 IC2.37
LED_T_RANGE_R
  Top 0.254: 33.5,67.94 33.02,67.47 30.32,64.77 30.32,62.07 30.16,61.91 R19.1 | 33.5,67.94 | 33.5,67.94 36.51,67.94 37.15,68.58 48.58,68.58 49.69,69.69 49.87,69.87 IC2.38
LED_X_DV  (via drill 0.5)
  Top 0.254: IC2.62 55.99,81.81 55.88,81.92 55.88,83.03 57.63,84.77 58.42,84.77 60.96,87.31 66.36,87.31 67.31,86.36 68.58,86.36 69.69,87.47 v75.25,87.47 | v75.25,93.03 76.23,94.02 R5.1
  Bottom 0.254: v75.25,87.47 v75.25,93.03
LED_X_EXT_G
  Top 0.254: IC2.55 57.1,78.26 58.58,78.26 62.23,74.61 62.23,72.07 61.75,71.6 61.75,66.67 60.48,65.41 55.72,65.41 52.39,62.07 52.39,55.09 48.26,50.96 48.26,46.35 46.99,45.09 R36.1
LED_X_MODE_G
  Top 0.254: IC2.59 60.34,80.31 60.96,79.69 71.12,79.69 74.3,76.52 80.01,76.52 83.86,80.36 R12.1
LED_X_MODE_R
  Top 0.254: IC2.61 60.62,81.31 61.28,80.64 72.55,80.64 76.04,77.15 79.69,77.15 82.52,79.97 R11.1
LED_X_RANGE_G
  Top 0.254: IC2.57 60.08,79.31 60.64,78.74 70.8,78.74 71.6,77.95 71.6,73.5 64.17,66.08 R17.1
LED_X_RANGE_R
  Top 0.254: IC2.56 59.94,78.81 60.48,78.26 70.64,78.26 71.12,77.79 71.12,73.66 64.45,66.99 64.42,66.96 R15.1
MORPH_IN
  Top 0.254: J1.P3 R64.2
  Top 0.305: J1.P3 7.3,31.11 5.93,29.74 C53.1
MORPH_IN1  (via drill 0.5)
  Top 0.254: v27.62,18.1 26.99,18.73 26.99,27.15 25.88,28.26 25.88,34.45 25.08,35.24 25.08,39.05 26.67,40.64 27.62,40.64 29.53,42.55 29.53,45.09 27.62,46.99 22.23,46.99 21.27,47.94 v19.37,47.94 | R35.2 19.37,44.48 v19.37,46.04 | J7.P3 58.1,16.51 60.43,18.84 C55.1
  Bottom 0.254: J7.P3 46.35,16.51 45.09,17.78 27.94,17.78 v27.62,18.1 | v19.37,47.94 v19.37,46.04
MORPH_IN3
  Top 0.254: R65.2 18.72,31.07 18.72,28.27 17.78,27.34 17.78,16.51
  Top 0.305: C56.1 15.14,16.51 17.78,16.51 J4.P3
MORPH_IN4  (via drill 0.5)
  Top 0.254: v18.1,47.94 19.05,48.9 20,48.9 20.32,48.58 21.59,48.58 22.54,47.62 27.94,47.62 30.16,45.4 30.16,42.23 27.94,40.01 26.99,40.01 25.72,38.73 25.72,35.4 26.51,34.61 26.51,28.57 27.62,27.46 27.62,20 v28.26,19.37 | R34.2 18.26,44.48 18.26,45.88 v18.1,46.04 | C57.1 62.02,15.56 63.5,15.56 64.45,16.51 J8.P3
  Bottom 0.254: J8.P3 58.42,16.51 57.15,17.78 55.88,17.78 55.24,17.14 46.67,17.14 45.4,18.41 29.21,18.41 v28.26,19.37 | v18.1,47.94 v18.1,46.04
MORPH_IN5  (via drill 0.5)
  Top 0.254: v26.67,16.51 26.67,18.41 26.35,18.73 26.35,25.24 24.61,26.99 24.61,34.13 23.81,34.92 23.81,39.69 26.04,41.91 26.99,41.91 28.26,43.18 28.26,44.45 26.99,45.72 24.13,45.72 23.94,45.53 R32.2 | J6.P3 45.72,16.51 49.85,20.64 C54.1
  Bottom 0.254: J6.P3 43.5,16.51 42.86,17.14 34.92,17.14 33.02,15.24 31.75,15.24 30.48,16.51 v26.67,16.51
MORPH_IN6  (via drill 0.5)
  Top 0.254: R66.2 23.81,31.08 23.81,26.83 25.72,24.92 v25.72,18.1 25.72,16.51 24.19,14.98 C58.1
  Bottom 0.254: v25.72,18.1 26.35,18.1 27.3,17.14 30.8,17.14 31.43,16.51 J5.P3
MORPH_IN7  (via drill 0.5)
  Top 0.254: v29.21,20.32 28.26,21.27 28.26,27.78 27.15,28.89 27.15,34.77 26.19,35.72 26.19,38.26 27.3,39.37 28.26,39.37 30.8,41.91 30.8,45.72 28.26,48.26 22.86,48.26 21.91,49.21 20.64,49.21 20.32,49.53 18.73,49.53 18.1,48.9 16.99,48.9 13.21,45.12 R33.2 | J2.P3 83.5,28.26 v83.5,17.78
  Top 0.305: C45.1 85.94,31.11 J2.P3
  Bottom 0.254: v83.5,17.78 67.94,17.78 67.31,17.14 58.74,17.14 57.47,18.41 55.56,18.41 54.93,17.78 46.99,17.78 45.72,19.05 30.48,19.05 v29.21,20.32
N$1
  Top 0.254: SW1.L1 20.32,99.61 R1.2
N$2
  Top 0.254: R5.2 78.66,96.16 SW2.L1
N$3
  Top 0.254: R55.1 46.16,32.74 46.02,32.88 IC9.12
N$4
  Top 0.406: IC3.3 12.06,76.05 12.06,76.99 13.78,78.71 C14.1 14.82,78.74 L3.1
N$5
  Top 0.254: R71.1 19.97,29.84 R65.1 R58.2 C41.1 IC6.2
N$6  (via drill 0.6)
  Top 0.406: L2.2 16.89,85.47 15.56,84.14 L3.2
  Top 0.61: v19.68,91.12 19.05,90.49 13.34,90.49 12.89,90.94 C5.1 12.68,92.29 L1.1 | L2.2 17.05,86.68 v19.68,86.68 | v23.18,96.52 | v23.18,96.52 D1.C
  Bottom 0.61: v19.68,86.68 v19.68,91.12 23.18,94.61 v23.18,96.52
N$7
  Top 0.254: R7.1 53.66,89.66 53.66,88.27 52.37,86.97 IC2.6
N$8
  Top 0.254: R8.1 54.77,88.74 52.87,86.84 IC2.5
N$9
  Top 0.254: LED3.3 24.45,61.91 R19.2
N$10
  Top 0.406: L4.2 8.8,73.03 D2.A
N$11
  Top 0.254: R70.1 15.08,30.16 14.73,30.52 R64.1 R57.2 C40.1 14.42,33.97 IC5.2
N$12
  Top 0.254: LED3.1 28.29,63.85 R18.2
N$13
  Top 0.254: IC2.47 54.37,72.31 54.61,72.07 C20.1
N$14  (via drill 0.5)
  Top 0.254: v37.31,15.56 37.47,15.72 37.47,16.51 37.94,16.99 37.94,18.1 | 37.94,18.1 37.94,18.73 | 40.6,34.17 40.64,34.13 | 37.94,18.1 37.94,21.11 39.37,22.54 39.37,27.46 40.96,29.05 40.96,30.16 40.96,33.66 40.96,33.81 40.6,34.17 | 13.65,12.38 | 13.65,12.38 v13.97,12.7 | R85.2 | R85.2 13.65,12.38 | 40.6,34.17 R51.1 | IC9.1 40,34.17 40.6,34.17
  Bottom 0.254: v13.97,12.7 15.56,14.29 26.35,14.29 27.62,15.56 30.16,15.56 31.43,14.29 33.34,14.29 34.29,15.24 34.61,15.24 | 34.61,15.24 35.08,15.24 | v37.31,15.56 36.99,15.24 34.61,15.24
N$15
  Top 0.254: R72.1 22.58,29.84 R66.1 R59.2 C42.1 IC6.6
N$16
  Top 0.254: LED1.3 3.85,86.96 R9.2
N$17
  Top 0.254: R28.1 16.99,44.48 R34.1 R40.2 C31.1 IC5.9
N$18
  Top 0.254: LED2.3 81.31,86.96 R11.2
N$19
  Top 0.254: C15.1 43.74,75.81 IC2.31
N$20
  Top 0.254: LED2.1 85.06,86.96 R12.2
N$21
  Top 0.254: LED4.3 61.91,63.5 63.18,64.77 R15.2
N$22
  Top 0.254: LED1.1 7.58,86.96 R10.2
N$23
  Top 0.254: LED4.1 65.37,64.17 R17.2
N$24
  Top 0.254: J10.P3 10.16,1.91 13.65,5.4 R85.1
N$25
  Top 0.254: C30.1 R39.2 R33.1 15.68,44.45 R30.1 | C30.1 14.45,41.88 | IC5.13 C30.1
N$26
  Top 0.254: R50.1 R51.2 39.41,34.96 39.05,34.61 39.05,33.81 39.34,33.53 IC9.2
N$27
  Top 0.254: R29.1 20.64,44.48 R35.1 R41.2 C32.1 20,41.31 19.97,41.28 IC6.13
N$28
  Top 0.254: LED6.2 2.86,12.06 R82.2
N$29
  Top 0.254: R56.1 39.25,32.74 39.37,32.86 39.38,32.88 IC9.3
N$30
  Top 0.254: IC9.7 IC9.6
N$31
  Top 0.254: 23.18,44.48 R32.1 R31.1 21.91,43.22 R42.2 C33.1 22.54,41.31 22.57,41.28 IC6.9
N$32
  Top 0.61: C3.1 12.78,94.19 L1.2 8.37,94.19 7.3,95.25 IC1.1
N$33
  Top 0.254: R2.1 51.75,97.47 53.5,99.22 60.8,99.22 JP2.2
N$34  (via drill 0.5)
  Top 0.254: v39.37,15.4 39.37,15.56 39.37,15.72 39.37,16.51 38.89,16.99 38.89,17.14 38.89,20.8 40.32,22.23 40.32,27.15 41.91,28.73 41.91,29.84 41.91,33.81 41.91,35.08 42.39,35.56 | 42.39,35.56 | 42.39,35.56 44.13,35.56 44.29,35.4 44.45,35.4 R52.1 44.77,35.37 44.77,34.92 45.42,34.27 IC9.14 | v26.04,12.7 25.72,12.38 R86.2
  Bottom 0.254: v26.04,12.7 27.94,14.61 29.84,14.61 31.11,13.34 33.66,13.34 34.45,14.13 37.62,14.13 38.1,14.13 v39.37,15.4
N$35
  Top 0.254: R49.1 R52.2 46,34.96 46.35,34.61 46.35,33.81 46.07,33.53 IC9.13
N$36  (via drill 0.5)
  Top 0.254: J9.P3 79.69,16.51 73.98,22.23 v73.98,22.54 | v35.4,23.02 35.72,23.34 35.72,25.88 34.92,26.67 34.92,33.18 37.31,35.56 37.31,41.91 38.1,42.7 38.1,46.83 40.13,48.86 R27.1
  Bottom 0.254: v73.98,22.54 73.66,22.86 67.94,22.86 66.04,24.77 59.05,24.77 57.15,22.86 55.88,22.86 53.98,24.77 46.99,24.77 45.09,22.86 43.81,22.86 41.91,24.77 37.15,24.77 v35.4,23.02
N$37
  Top 0.254: R67.1 46.16,31.71 46.02,31.58 IC9.10
N$38  (via drill 0.5)
  Top 0.254: R87.2 26.99,5.71 26.99,7.3 27.94,8.26 v34.92,8.26 | v41.27,15.24 41.27,21.27 43.18,23.18 43.18,29.21 44.25,30.28 IC9.8 45.42,29.54 R69.1
  Bottom 0.254: v34.92,8.26 38.58,11.91 38.58,13.02 39.53,13.97 40.16,13.97 | 40.16,13.97 | 40.16,13.97 | 40.16,13.97 41.27,15.08 v41.27,15.24
N$39
  Top 0.254: J11.P3 22.86,1.91 24.77,3.81 25.72,4.76 R86.1 25.5,6.45
N$40
  Top 0.254: R87.1 27.09,2.86 27.62,2.86 28.57,1.91 J12.P3
N$41
  Top 0.254: R75.1 R69.2 46.64,29.72 46.35,30 46.35,30.48 45.91,30.93 IC9.9
N$42
  Top 0.254: LED5.1 | LED5.1 R36.2
N$44
  Top 0.254: LED7.2 14.92,12.06 R83.2
N$45  (via drill 0.5)
  Top 0.254: v66.99,31.11 65.94,31.11 R62.2 65.69,31.5 C43.2 66.18,33.2 IC7.7 | v50.01,29.84 50.63,30.46 IC10.5
  Bottom 0.254: v66.99,31.11 66.67,30.8 63.82,30.8 62.87,29.84 v50.01,29.84
N$46
  Top 0.254: J9.P2 76.52,24.13 76.23,23.85 R77.2
N$47
  Top 0.254: J3.P2 9.21,24.13 10.51,25.43 R76.2
N$48
  Top 0.254: LED8.2 26.99,12.06 R84.2
N$49
  Top 0.254: 69.22,1.91 J15.P3 78.74,1.91 80.01,3.17 83.5,3.17 84.77,4.45 84.77,12.7 82.87,14.61 79.85,14.61 72.07,22.38 72.07,27.62 68.9,30.8 68.9,33.34 68.58,33.66 68.58,35.24 69.22,35.88 69.22,37.78 69.64,38.2 R46.1 69.53,39.16 69.53,39.69 70.01,40.16 71.91,40.16 72.39,39.69 R44.1
N$50
  Top 0.254: R24.2 R26.2 | R24.2 35.4,50.52 D4.C | Q2.B 34.92,51.44 35.44,50.92 R24.2
N$51
  Top 0.254: R3.1 52.86,97.31 53.34,97.79 JP2.1
N$52
  Top 0.254: D5.C 37.82,50.48 R25.2 | R25.2 R27.2 | Q3.B 38.42,51.44 38.93,50.92 R25.2
N$53
  Top 0.254: 44.47,1.89 J13.P3 54.61,1.91 55.88,3.17 57.15,3.17 57.78,2.54 66.36,2.54 67.63,3.81 69.53,3.81 70.17,3.17 78.11,3.17 79.38,4.45 82.87,4.45 83.5,5.08 83.5,12.06 82.23,13.34 79.53,13.34 70.8,22.07 70.8,26.99 67.63,30.16 64.61,30.16 63.92,30.85 R62.1 63.88,31.47 R60.1
N$54
  Top 0.254: R44.2 C35.1 73.62,37.91 73.03,37.31 73.03,36.87 R48.1 73.03,36.86 IC7.13
N$56
  Top 0.61: JP4.9 JP4.10 25.4,102.87 24.77,102.23 D1.A
N$57  (via drill 0.5)
  Top 0.254: J3.P3 13.34,21.59 v13.34,25.4 | v34.77,24.29 34.92,24.45 | 34.92,24.45 | 34.92,24.45 34.92,25.72 34.29,26.35 34.29,33.18 36.83,35.72 36.83,42.07 37.62,42.86 37.62,45.24 36.64,46.23 R26.1
  Bottom 0.254: v13.34,25.4 13.97,24.77 18.41,24.77 19.05,24.13 19.05,23.5 19.68,22.86 20.95,22.86 22.86,24.77 30.48,24.77 31.11,24.13 31.11,23.5 31.75,22.86 33.34,22.86 v34.77,24.29
N$58
  Top 0.254: J16.P3 80.96,1.91 81.6,2.54 83.82,2.54 85.41,4.13 85.41,13.02 83.19,15.24 80.01,15.24 72.71,22.54 72.71,30.16 73.72,31.17 R63.1 73.75,31.47 R61.1
N$59
  Top 0.254: 74.89,32.7 R61.2 73.34,32.67 C44.1 73.31,33.37 73.03,33.66 73.03,34.26 R53.1 73.03,34.26 IC7.9
N$60
  Top 0.254: R43.2 C34.1 64.17,37.91 64.77,37.31 64.77,36.94 64.81,36.9 R47.1 64.77,36.86 IC7.2
N$61
  Top 0.254: R60.2 62.9,32.7 C43.1 64.45,32.74 64.89,33.18 R54.1 65.34,34.26 IC7.6
N$62
  Top 0.254: R8.2 56.83,88.74 57.47,89.38 57.47,93.34 58.35,94.23 Q1.3 59.07,94.26 C4.2
N$63
  Top 0.254: 56.5,1.89 J14.P3 66.67,1.91 67.94,3.17 69.22,3.17 69.85,2.54 78.42,2.54 79.69,3.81 83.19,3.81 84.14,4.76 84.14,12.38 82.55,13.97 79.69,13.97 71.44,22.23 71.44,27.3 68.26,30.48 68.26,33.02 67.94,33.34 67.94,35.56 68.58,36.2 68.58,37.78 68.16,38.2 R45.1 68.26,39.16 68.26,39.69 67.79,40.16 66.04,40.16 65.56,39.69 R43.1
N$64
  Top 0.406: D2.C 2.54,73.03 1.59,73.98 1.59,90.17 5.08,93.66 5.08,102.87 6.99,104.78 8.26,104.78 35.56,104.78 36.83,103.5 JP4.2 JP4.1
N$65
  Top 0.254: C6.2 53.06,91.83 Q1.1 54.63,90.78 54.93,90.49 54.93,89.73 R7.2
N$67
  Top 0.254: R78.1 LED9.2 40.64,12.7 41.91,13.97 44.13,13.97 50.8,20.64 50.8,29.37 51.25,29.82 IC10.6
N$68
  Top 0.254: LED9.1 42.86,13.34 44.45,13.34 51.44,20.32 51.44,28.89 51.44,29.05 51.55,29.16 IC10.7
N$70  (via drill 0.5)
  Top 0.254: v51.91,33.97 51.59,33.97 51.12,33.5 51.12,32.07 51.42,31.77 IC10.3 | R45.2 66.18,38.77 66.18,38.26 | C34.2 65.53,38.26 66.18,38.26 | 66.18,38.26 IC7.1 66.95,37.51 v67.63,36.83
  Bottom 0.254: v67.63,36.83 67.31,36.51 64.45,36.51 61.28,33.34 52.55,33.34 v51.91,33.97
N$71
  Top 0.254: LED10.2 R79.1 50.13,13.3 52.07,15.24 52.07,27.94 53.18,29.05 53.18,32.07 52.83,32.41 IC10.2
N$72
  Top 0.254: LED10.1 53.34,12.7 52.7,13.34 52.7,27.62 53.82,28.73 53.82,32.38 53.14,33.06 IC10.1
N$73  (via drill 0.5)
  Top 0.254: v59.85,34.29 58.58,33.02 58.58,32.07 58.28,31.77 IC10.12 | R46.2 71.61,38.77 71.61,38.26 | 71.61,38.26 IC7.14 70.85,37.51 v70.17,36.83 | C35.2 72.27,38.26 71.61,38.26
  Bottom 0.254: v59.85,34.29 61.28,34.29 64.14,37.15 66.67,37.15 67.31,37.78 68.26,37.78 69.22,36.83 v70.17,36.83
N$74
  Top 0.254: LED11.2 R80.1 62.2,13.37 61.91,13.65 61.59,13.65 57.78,13.65 57.15,14.29 55.88,14.29 53.98,16.19 53.98,19.37 53.98,25.72 53.98,26.99 56.36,29.37 56.36,32.07 56.7,32.41 IC10.13
N$75
  Top 0.254: LED11.1 66.04,12.38 65.41,11.75 58.74,11.75 56.83,13.65 55.56,13.65 53.34,15.88 53.34,26.04 53.34,27.3 55.72,29.69 55.72,32.38 56.4,33.06 IC10.14
N$76  (via drill 0.5)
  Top 0.254: v70.64,30.8 71.28,31.43 R63.2 72.11,31.52 C44.2 71.61,33.2 IC7.8 | v60.48,28.57 58.59,30.46 IC10.10
  Bottom 0.254: v60.48,28.57 61.12,29.21 63.18,29.21 64.14,30.16 67.31,30.16 68.58,31.43 70.01,31.43 v70.64,30.8
N$77
  Top 0.254: LED12.2 R81.1 74.26,13.37 73.98,13.65 71.75,13.65 70.8,14.61 70.8,16.83 69.22,18.41 66.36,18.41 58.58,26.19 58.58,29.53 58.29,29.82 IC10.9
N$78
  Top 0.254: LED12.1 78.42,12.38 77.79,11.75 71.12,11.75 68.9,13.97 62.55,13.97 62.23,14.29 58.1,14.29 57.47,14.92 56.2,14.92 55.88,15.24 54.61,16.51 54.61,20.32 54.61,26.04 54.61,26.67 57.1,29.16 IC10.8
NORMALIZATION_PROBE  (via drill 0.5)
  Top 0.254: R76.1 v13.34,26.67 | v33.97,25.4 33.66,25.72 33.66,33.18 35.24,34.77 35.88,35.4 36.35,35.88 36.35,38.58 | IC2.39 50.37,67.42 50.8,66.99 50.8,65.56 48.58,63.34 48.58,57.78 47.94,57.15 33.5,57.15 33.34,56.99 D3.3 33.34,52.86 32.86,52.39 32.86,49.37 37.15,45.09 37.15,43.02 36.35,42.23 36.35,38.58 | v75.25,26.35 R77.1 | 36.35,38.58
  Bottom 0.254: v13.34,26.67 14.61,25.4 v33.97,25.4 74.3,25.4 v75.25,26.35
RESET
  Top 0.254: IC2.7 51.91,84.95 51.91,84.14 52.39,83.66 54.93,83.66 57.31,86.04 57.78,86.04 60.33,88.58 63.82,88.58 66.04,90.81 66.64,90.81 R6.1 C7.1 67.66,90.81 74.61,90.81 77.15,88.27 JP1.4
RX  (via drill 0.5)
  Top 0.254: v52.7,90.49 52.07,91.12 52.07,94.46 52.86,95.25 R3.2 | v52.07,77.47 52.37,77.17 IC2.43
  Bottom 0.254: v52.7,90.49 52.7,89.22 51.44,87.95 51.44,78.11 v52.07,77.47
SW_T_DV  (via drill 0.5)
  Top 0.254: SW1.P2 SW1.P5 16.39,96.04 18.89,96.04 25.08,89.85 35.24,89.85 36.51,88.58 v36.51,88.27 | v37.47,73.82 37.62,73.98 39.53,73.98 | 39.53,73.98 | 39.53,73.98 41.86,76.31 IC2.30
  Bottom 0.254: v36.51,88.27 36.51,87 36.83,86.68 36.83,74.45 v37.47,73.82
SW_T_MODE  (via drill 0.5)
  Top 0.254: IC2.35 48.37,71.23 47.62,70.48 36.71,70.48 36.39,70.48 35.4,70.48 34.92,70.96 v34.92,72.07 | v33.66,87.31 33.34,87.63 33.02,87.95 24.13,87.95 19.37,87.95 12.06,87.95 11.75,87.63 10.48,86.36 9.53,85.41 9.53,81.6 8.26,80.33 5.08,80.33 3.49,80.33 3.45,80.37 3.45,80.96 | 3.45,80.96 SW3.3 | SW3.4 3.45,80.96
  Bottom 0.254: v34.92,72.07 34.92,81.92 34.92,85.57 33.66,86.84 v33.66,87.31
SW_T_RANGE  (via drill 0.5)
  Top 0.254: SW5.3 SW5.4 | v26.67,65.41 27.3,66.04 29.84,66.04 33.02,69.22 35.88,69.22 36.51,69.85 37.15,69.85 47.94,69.85 48.87,70.78 IC2.36
  Bottom 0.254: SW5.4 26.67,57.51 v26.67,65.41
SW_X_DV
  Top 0.254: 53.34,85.02 IC2.4 53.37,85.91 54.77,87.31 57.31,87.31 59.85,89.85 61.91,89.85 62.23,90.17 62.23,91.76 64.45,93.98 71.12,93.98 73.66,96.52 SW2.P5 SW2.P2
SW_X_EXT
  Top 0.254: SW7.3 SW7.4 50.08,53.42 51.91,55.24 51.91,62.23 55.56,65.88 60.33,65.88 61.28,66.83 61.28,71.75 61.75,72.23 61.75,74.45 58.42,77.79 57.07,77.79 IC2.54
SW_X_MODE
  Top 0.254: IC2.2 54.37,86.12 55.09,86.84 57.63,86.84 60.01,89.22 63.66,89.22 65.88,91.44 74.93,91.44 84.45,91.44 86.68,89.22 86.68,83.19 85.48,81.99 SW4.4 SW4.3
SW_X_RANGE
  Top 0.254: IC2.58 60.21,79.81 60.8,79.22 70.96,79.22 | SW6.4 67.59,55.52 68.58,56.52 68.58,60.96 67.31,62.23 67.31,68.58 72.07,73.34 72.07,78.11 70.96,79.22 | 70.96,79.22
  Bottom 0.254: SW6.3 SW6.4
SWCLK  (via drill 0.5)
  Top 0.254: IC2.49 58.04,75.31 58.42,74.93 v58.42,74.3 | v65.09,85.72 65.41,85.41 66.67,85.41 66.99,85.09 72.07,85.09 73.34,83.82 JP1.3
  Bottom 0.254: v58.42,74.3 60.01,74.3 60.64,74.93 60.64,75.25 65.09,79.69 v65.09,85.72
SWDIO  (via drill 0.5)
  Top 0.254: v59.37,73.34 58.1,73.34 56.83,74.61 54.29,74.61 53.87,74.19 IC2.46 | v66.04,84.45 72.07,84.45 75.25,81.28 JP1.2
  Bottom 0.254: v59.37,73.34 59.69,73.66 60.33,73.66 61.28,74.61 61.28,74.93 65.72,79.38 65.72,83.19 66.04,83.5 v66.04,84.45
T_CLOCK
  Top 0.254: IC2.40 50.87,67.56 51.28,67.15 51.28,65.41 49.05,63.18 49.05,57.63 48.1,56.67 36.35,56.67 35.91,56.23 R22.1 35.91,54.32 Q2.C
TX  (via drill 0.5)
  Top 0.254: v51.75,89.53 51.44,89.85 51.44,94.61 51.75,94.93 R2.2 | v50.8,77.15 51.87,76.08 IC2.42
  Bottom 0.254: v51.75,89.53 50.8,88.58 v50.8,77.15
VCC  (via drill 0.5, 0.6)
  Top 0.254: IC7.4 v64.77,35.56 64.14,34.92 C39.1 | v49.21,32.7 49.21,31.75 49.81,31.15 C48.1 50.36,31.11 IC10.4 | 38.29,31.75 C50.1 | IC9.4 39.21,32.23 38.73,31.75 38.29,31.75 | 38.29,31.75 37.62,31.75 37.15,32.23 v37.15,32.7
  Top 0.406: v4.13,33.02 4.13,33.66 3.17,34.61 3.17,56.2 10.79,63.82 10.79,75.25 8.89,77.15 8.89,79.38 10.79,81.28 10.79,84.45 12.21,85.87 C11.+ 14.33,85.87 L2.1
  Bottom 0.406: v4.13,33.02 9.21,33.02 9.53,32.7 v37.15,32.7 v49.21,32.7 61.91,32.7 v64.77,35.56
VEE  (via drill 0.5)
  Top 0.254: IC7.11 v73.03,35.56 C37.2 | 57.5,31.1 IC10.11 59.5,31.11 C49.2 59.57,31.11 60.33,31.11 v60.96,31.75 | R68.1 31.43,30.2 v31.43,31.43
  Top 0.406: v2.86,32.07 2.86,33.66 2.22,34.29 2.22,57.47 1.59,58.1 1.59,59.69 8.08,66.19 C22.- 8.08,69.25 L4.1
  Bottom 0.305: 7.3,32.07 7.62,32.38 8.89,32.38 9.53,31.75
  Bottom 0.406: v2.86,32.07 7.3,32.07 | 9.53,31.75 31.43,31.75 | 31.43,31.75 v31.43,31.43 | 31.43,31.75 v60.96,31.75 62.23,31.75 66.04,35.56 v73.03,35.56
VREF  (via drill 0.5)
  Top 0.254: v69.85,42.23 70.17,41.91 74.3,41.91 77.15,39.05 77.15,32.7 77.75,32.1 R74.2 | v67.31,41.27 66.67,41.91 66.67,44.77 56.83,54.61 56.83,59.69 56.55,59.97 C25.1 56.5,60.85 IC4.3
  Bottom 0.254: v67.31,41.27 68.26,42.23 v69.85,42.23
VREF_BIAS  (via drill 0.5)
  Top 0.254: v67.31,32.7 67.31,34.92 | v70.48,32.7 70.48,34.92 | 70.48,34.92 70.48,35.88 70.82,36.21 IC7.12 | 67.31,34.92 67.31,35.88 66.98,36.21 IC7.3 | R74.1 R73.2 C51.1 75.21,30.45 76.2,31.43 v76.2,32.7 | IC7.5 66.19,34.92 67.31,34.92 | 70.48,34.92 70.5,34.91 IC7.10
  Bottom 0.254: v67.31,32.7 v70.48,32.7 v76.2,32.7
X_CLOCK
  Top 0.254: IC2.41 51.37,67.69 51.75,67.31 51.75,65.25 49.53,63.02 49.53,57.47 48.26,56.2 40.16,56.2 39.85,55.88 R23.1 39.34,54.32 Q3.C

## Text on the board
bNames: Red Stripe | +12V | GND | GND | GND | -12V | Marbles | cc-by-sa Émilie Gillet | 2017. v7
tStop: Marbles | cc-by-sa Émilie Gillet | 2017. v7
